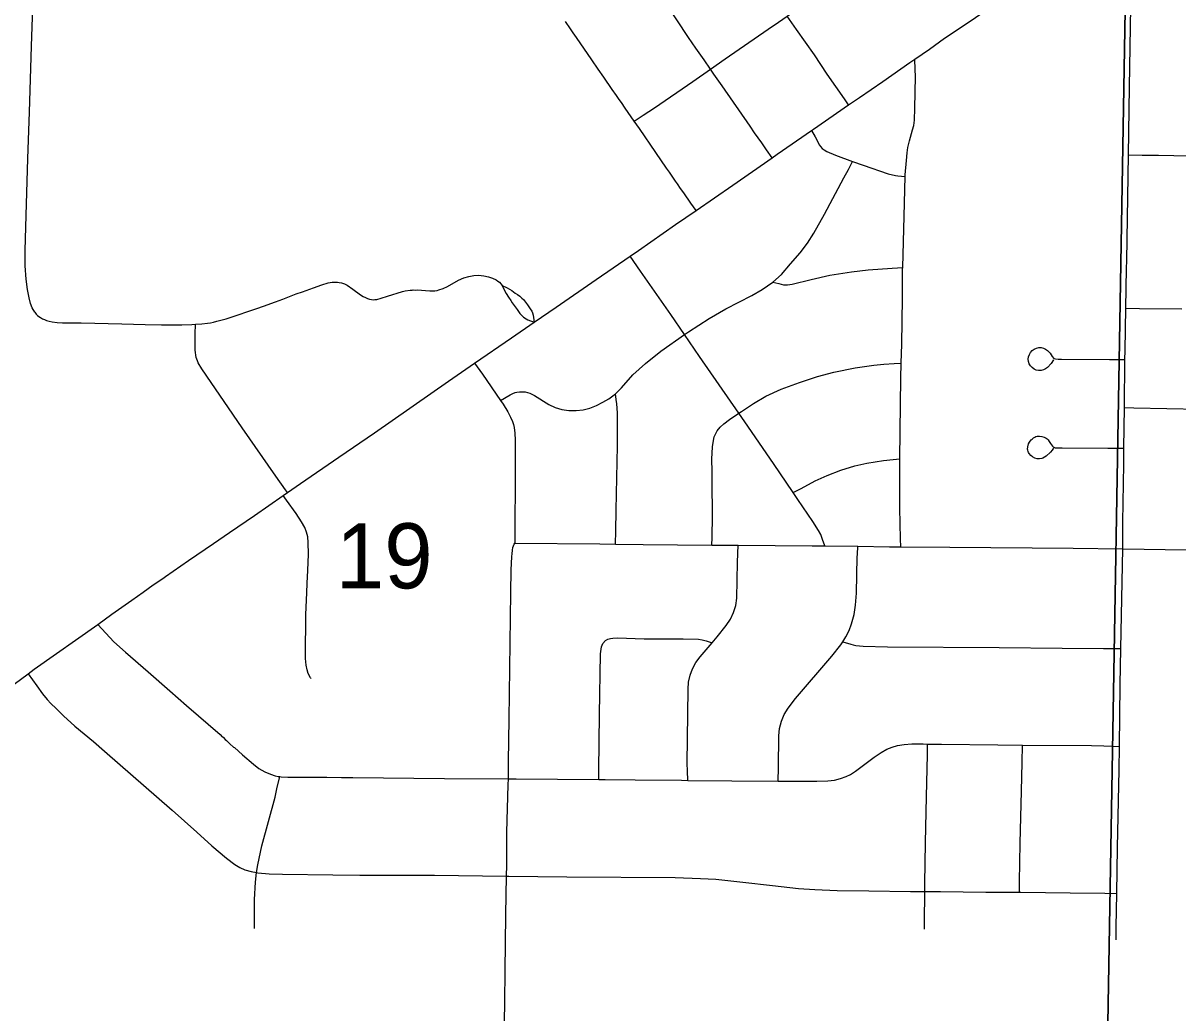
# Model space of a CAD drawing. Extents: x 0 to 34, y 0 to 22.
# Drawn here: x 5.989 to 6.731, y 16.761 to 17.398 of the extents above; entities that cross this region are included whole.
import ezdxf

# ---------------------------------------------------------------- set-up
doc = ezdxf.new("R2010")
doc.units = 0
for name, color, linetype in [('GM_X_City_Street', 7, 'Continuous'), ('GM_X_Corporation', 7, 'Continuous'), ('GM_X_County_Road', 7, 'Continuous'), ('GM_X_Section_Text', 7, 'Continuous')]:
    doc.layers.add(name, color=color, linetype=linetype)

msp = doc.modelspace()

# ---------------------------------------------------------------- linework, layer by layer
at = {"layer": 'GM_X_City_Street'}
for points in [[(6.38189, 17.33453), (6.38766, 17.33835), (6.39487, 17.34314), (6.4195, 17.35995), (6.43091, 17.36795), (6.44036, 17.37457), (6.46796, 17.39369), (6.47464, 17.39822), (6.48015, 17.402), (6.50541, 17.41931), (6.52913, 17.43567), (6.54378, 17.44578), (6.56925, 17.46352), (6.58463, 17.47403), (6.5991, 17.48358), (6.60985, 17.49085), (6.62182, 17.49957), (6.63111, 17.50666), (6.63429, 17.50944), (6.63584, 17.51122), (6.63775, 17.51441), (6.63892, 17.51638)], [(5.9964, 17.21165), (5.99476, 17.21456), (5.99369, 17.21737), (5.99271, 17.22088), (5.99163, 17.2263), (5.99074, 17.23302), (5.99027, 17.24148), (5.99027, 17.25128), (5.99077, 17.27388), (5.99199, 17.31055), (5.99292, 17.34039), (5.99424, 17.38264), (5.99507, 17.40749)], [(6.47049, 17.31094), (6.46694, 17.31599), (6.46384, 17.32051), (6.45924, 17.327), (6.45629, 17.33138), (6.43839, 17.35732), (6.4331, 17.36478), (6.43091, 17.36795), (6.42684, 17.3739), (6.42147, 17.38152), (6.41679, 17.38838), (6.4022, 17.41033)], [(6.42164, 17.27717), (6.41834, 17.2818), (6.41366, 17.28836), (6.4117, 17.29114), (6.40968, 17.29417), (6.40841, 17.29594), (6.40626, 17.2991), (6.40443, 17.30175), (6.40266, 17.3044), (6.39583, 17.31439), (6.38523, 17.32973), (6.38189, 17.33453), (6.37609, 17.34285), (6.37364, 17.34649), (6.37224, 17.34846), (6.37048, 17.35091), (6.36774, 17.35478), (6.36231, 17.3628), (6.3587, 17.36792), (6.35465, 17.37391), (6.34472, 17.38825), (6.34263, 17.39128), (6.34092, 17.3938), (6.33764, 17.39854)], [(6.51973, 17.34495), (6.51697, 17.34895), (6.50601, 17.36481), (6.49768, 17.37715), (6.48623, 17.39336), (6.48015, 17.402)], [(6.55323, 17.06089), (6.55312, 17.06606), (6.55268, 17.08567), (6.55256, 17.10743), (6.55266, 17.11748), (6.55304, 17.15246), (6.55333, 17.1694), (6.55359, 17.17887), (6.55392, 17.19114), (6.55433, 17.22068), (6.55444, 17.23935), (6.55448, 17.24041), (6.55551, 17.27354), (6.55613, 17.299), (6.55616, 17.29998), (6.55689, 17.30927), (6.55728, 17.31423), (6.55785, 17.31768), (6.55891, 17.32179), (6.5608, 17.32887), (6.56154, 17.33183), (6.56203, 17.3352), (6.56236, 17.34296), (6.5628, 17.36316), (6.5626, 17.36782), (6.56232, 17.37445)], [(6.49593, 17.32857), (6.49817, 17.32437), (6.50096, 17.31914), (6.50165, 17.31818), (6.50272, 17.31693), (6.50388, 17.31611), (6.50563, 17.31511), (6.51132, 17.3126), (6.5223, 17.30863), (6.52898, 17.30622), (6.54522, 17.30062), (6.54976, 17.29954), (6.55132, 17.29941), (6.55613, 17.299)], [(6.69967, 17.31278), (6.70843, 17.31268), (6.71892, 17.31257), (6.7288, 17.31245), (6.74446, 17.31198), (6.76906, 17.31145), (6.80488, 17.3108), (6.8106, 17.31058), (6.81482, 17.31042)], [(6.29592, 17.15499), (6.30204, 17.15853), (6.30385, 17.15954), (6.3053, 17.16011), (6.30635, 17.16032), (6.30808, 17.1605), (6.30994, 17.16054), (6.31161, 17.16041), (6.31312, 17.16007), (6.31475, 17.15955), (6.31769, 17.15816), (6.32694, 17.15236), (6.33101, 17.1504), (6.33536, 17.14916), (6.33986, 17.14852), (6.34442, 17.14846), (6.34893, 17.14895), (6.35335, 17.15005), (6.3576, 17.15167), (6.36163, 17.1538), (6.36554, 17.15612), (6.36892, 17.15852), (6.36972, 17.15929), (6.37356, 17.16303), (6.38103, 17.17142), (6.38919, 17.17872), (6.39892, 17.18658), (6.41418, 17.19733), (6.41679, 17.19917), (6.42997, 17.20756), (6.4408, 17.21378), (6.45756, 17.22242), (6.46419, 17.2264), (6.47088, 17.23107), (6.47651, 17.23596), (6.48242, 17.24286), (6.48852, 17.24985), (6.4932, 17.25598), (6.4974, 17.26245), (6.50415, 17.27466), (6.51659, 17.29804), (6.51954, 17.30353), (6.5223, 17.30863)], [(6.50443, 17.0615), (6.50289, 17.06565), (6.50174, 17.06877), (6.50039, 17.07143), (6.4966, 17.07712), (6.4871, 17.09129), (6.48403, 17.09579), (6.47134, 17.11439), (6.45298, 17.14119), (6.44912, 17.14676), (6.42387, 17.18323), (6.41418, 17.19733), (6.40539, 17.21013), (6.38579, 17.23817), (6.37917, 17.24765)], [(5.9964, 17.21165), (5.99729, 17.21051), (5.99819, 17.20956), (5.9989, 17.209), (6.00005, 17.20824), (6.00124, 17.20752), (6.00256, 17.20693), (6.00399, 17.20633), (6.00566, 17.20586), (6.00758, 17.20544), (6.01069, 17.20503), (6.01421, 17.20491), (6.01768, 17.20485), (6.02222, 17.2048), (6.02619, 17.20481), (6.05235, 17.20419), (6.06727, 17.20382), (6.07784, 17.20352), (6.09087, 17.20357), (6.0973, 17.20378), (6.09975, 17.20396), (6.10382, 17.20427), (6.10746, 17.2047), (6.10927, 17.20496), (6.11129, 17.20534), (6.11347, 17.20586), (6.1194, 17.2075), (6.12648, 17.20979), (6.1341, 17.21241), (6.13927, 17.21415), (6.14347, 17.21568), (6.1511, 17.21841), (6.15582, 17.22014), (6.16447, 17.22341), (6.16859, 17.2248), (6.17556, 17.22736), (6.18092, 17.22931), (6.18513, 17.23058), (6.18771, 17.23092), (6.19096, 17.23091), (6.19221, 17.23076), (6.19356, 17.23052), (6.19546, 17.23002), (6.19725, 17.22916), (6.20097, 17.22661), (6.20588, 17.22285), (6.20758, 17.22174), (6.209, 17.22105), (6.21039, 17.22043), (6.21166, 17.22004), (6.21284, 17.21983), (6.21395, 17.21976), (6.21512, 17.21983), (6.21626, 17.21996), (6.21914, 17.22062), (6.22319, 17.22205), (6.23277, 17.22503), (6.23464, 17.22546), (6.23782, 17.22587), (6.23909, 17.2259), (6.23973, 17.22604), (6.241, 17.22597), (6.24228, 17.22603), (6.25035, 17.22549), (6.25253, 17.22543), (6.25373, 17.22548), (6.25516, 17.22572), (6.25624, 17.226), (6.25903, 17.22694), (6.26175, 17.22828), (6.26886, 17.23222), (6.27236, 17.23376), (6.27543, 17.23472), (6.27861, 17.23528), (6.28184, 17.23543), (6.28337, 17.23537), (6.28505, 17.23517), (6.28822, 17.23452), (6.29069, 17.23366), (6.29303, 17.23248), (6.29413, 17.23173), (6.29516, 17.23091), (6.29698, 17.22897)], [(6.47088, 17.23107), (6.47492, 17.23005), (6.47784, 17.22933), (6.48036, 17.22927), (6.48347, 17.22973), (6.49558, 17.23273), (6.50769, 17.23545), (6.52146, 17.2377), (6.53224, 17.23894), (6.54774, 17.23996), (6.55448, 17.24041)], [(6.29698, 17.22897), (6.29821, 17.22619), (6.29958, 17.22379), (6.30107, 17.2213), (6.30241, 17.21929), (6.30343, 17.21781), (6.30659, 17.21335), (6.30837, 17.21089), (6.30969, 17.20945), (6.31065, 17.20856), (6.31226, 17.20748), (6.31352, 17.20682), (6.3174, 17.20521)], [(6.29698, 17.22897), (6.30023, 17.22731), (6.30316, 17.22558), (6.30538, 17.22403), (6.30687, 17.22301), (6.30818, 17.222), (6.3095, 17.22081), (6.31054, 17.21981), (6.31315, 17.21647), (6.31503, 17.21379), (6.31596, 17.21232), (6.31644, 17.21131), (6.31687, 17.20975), (6.31723, 17.2067), (6.3174, 17.20521)], [(6.69799, 17.2142), (6.70666, 17.2141), (6.73401, 17.21379)], [(6.15885, 17.09579), (6.15755, 17.09762), (6.15133, 17.10636), (6.12977, 17.13746), (6.11816, 17.15432), (6.1097, 17.16659), (6.10376, 17.17536), (6.10155, 17.17919), (6.10092, 17.18048), (6.10049, 17.18151), (6.10015, 17.18263), (6.09986, 17.18407), (6.09963, 17.18571), (6.09954, 17.18728), (6.09953, 17.19291), (6.09962, 17.19756), (6.09975, 17.20396)], [(6.6514, 17.18106), (6.65, 17.17875), (6.64758, 17.17622), (6.64633, 17.1753), (6.64494, 17.17463), (6.64345, 17.17427), (6.6419, 17.17425), (6.64038, 17.17454), (6.63895, 17.17515), (6.63769, 17.17605), (6.63666, 17.17721), (6.63588, 17.17855), (6.6354, 17.18002), (6.63525, 17.18156), (6.63544, 17.18309), (6.63594, 17.18455), (6.63674, 17.18588), (6.63781, 17.18702), (6.63907, 17.18795), (6.64047, 17.18863), (6.64198, 17.189), (6.64351, 17.189), (6.64499, 17.18865), (6.64637, 17.18799), (6.64758, 17.18703), (6.64924, 17.18537), (6.65066, 17.18315), (6.6516, 17.18187), (6.65282, 17.18167), (6.65443, 17.1816), (6.65665, 17.18147), (6.68756, 17.1813), (6.69742, 17.18122)], [(6.4318, 17.06197), (6.4319, 17.06684), (6.43198, 17.07079), (6.43214, 17.07696), (6.43212, 17.08483), (6.43204, 17.09875), (6.43197, 17.1094), (6.43183, 17.11717), (6.43214, 17.12517), (6.43276, 17.12914), (6.43334, 17.13148), (6.43383, 17.13277), (6.43526, 17.13536), (6.43716, 17.13778), (6.43937, 17.13994), (6.44315, 17.14267), (6.44912, 17.14676), (6.45084, 17.14793), (6.45846, 17.15306), (6.46655, 17.15763), (6.47643, 17.16215), (6.48805, 17.1666), (6.49979, 17.17043), (6.51024, 17.17317), (6.52392, 17.17601), (6.53595, 17.17756), (6.54244, 17.1783), (6.54902, 17.17864), (6.55359, 17.17887)], [(6.36979, 17.06262), (6.36993, 17.0712), (6.37014, 17.08429), (6.37034, 17.09492), (6.37099, 17.1257), (6.37114, 17.14695), (6.37065, 17.15281), (6.37025, 17.1556), (6.36972, 17.15929)], [(6.69704, 17.15043), (6.70302, 17.15031), (6.74562, 17.14944), (6.79588, 17.14861), (6.80641, 17.14836), (6.81355, 17.1482)], [(6.65142, 17.1243), (6.65053, 17.12305), (6.64948, 17.12166), (6.64671, 17.11913), (6.64572, 17.11844), (6.64468, 17.11793), (6.64395, 17.11775), (6.64244, 17.11748), (6.6409, 17.11754), (6.6394, 17.11793), (6.63803, 17.11864), (6.63683, 17.11962), (6.63585, 17.12084), (6.63539, 17.12156), (6.63516, 17.12223), (6.63494, 17.12294), (6.63482, 17.12373), (6.63493, 17.12525), (6.63542, 17.12714), (6.63598, 17.12821), (6.63647, 17.1289), (6.63712, 17.12965), (6.63764, 17.13015), (6.63855, 17.13089), (6.63942, 17.13141), (6.64015, 17.13174), (6.64088, 17.13193), (6.64242, 17.13205), (6.64396, 17.13184), (6.64544, 17.13139), (6.64679, 17.13064), (6.6474, 17.13026), (6.64797, 17.12964), (6.64874, 17.12857), (6.64948, 17.12737), (6.65023, 17.12634), (6.65078, 17.12559), (6.65127, 17.12509), (6.65252, 17.1246), (6.65385, 17.12454), (6.65693, 17.12444), (6.68646, 17.12437), (6.69673, 17.12434)], [(6.48403, 17.09579), (6.4891, 17.09847), (6.49814, 17.10325), (6.50594, 17.1067), (6.51468, 17.11022), (6.5237, 17.11296), (6.53136, 17.11468), (6.54221, 17.11631), (6.54843, 17.11701), (6.55266, 17.11748)], [(6.17402, 16.97616), (6.1737, 16.97669), (6.17227, 16.97946), (6.17148, 16.98181), (6.17085, 16.98485), (6.17048, 16.98919), (6.17043, 16.99789), (6.17071, 17.00969), (6.17073, 17.014), (6.17074, 17.01709), (6.17093, 17.02206), (6.17134, 17.03137), (6.17163, 17.03759), (6.172, 17.04566), (6.17234, 17.05621), (6.17225, 17.06366), (6.17189, 17.06737), (6.17117, 17.07038), (6.16997, 17.07324), (6.16784, 17.07703), (6.1644, 17.08222), (6.15824, 17.09084), (6.15607, 17.09387)], [(6.29804, 16.73136), (6.29857, 16.76804), (6.29878, 16.78854), (6.29901, 16.80594), (6.29927, 16.82446), (6.29978, 16.84924), (6.29993, 16.85629), (6.29996, 16.87743), (6.30083, 16.90786), (6.3009, 16.91176), (6.3011, 16.92281), (6.30139, 16.95015), (6.30253, 17.03161), (6.3028, 17.04595), (6.30318, 17.05469), (6.30327, 17.05643), (6.30355, 17.05877), (6.30389, 17.06046), (6.30421, 17.06153), (6.30466, 17.06257), (6.30513, 17.06324)], [(6.41628, 16.91076), (6.41609, 16.91693), (6.41594, 16.92154), (6.41645, 16.96943), (6.41673, 16.97393), (6.41773, 16.97829), (6.41932, 16.98252), (6.4215, 16.98643), (6.42419, 16.99011), (6.43193, 16.99922), (6.43517, 17.00304), (6.44104, 17.01031), (6.44365, 17.01428), (6.44571, 17.01858), (6.44709, 17.02316), (6.44773, 17.02789), (6.44833, 17.05108), (6.4486, 17.06185)], [(6.47438, 16.91027), (6.47453, 16.91908), (6.47487, 16.9393), (6.47536, 16.94404), (6.47647, 16.94871), (6.47833, 16.95315), (6.48083, 16.95724), (6.4856, 16.96347), (6.50886, 16.99067), (6.51465, 16.9979), (6.51595, 16.99987), (6.518, 17.00301), (6.52004, 17.00708), (6.52165, 17.01136), (6.52322, 17.01728), (6.52423, 17.02333), (6.52471, 17.031), (6.52529, 17.05434), (6.52537, 17.05591), (6.52565, 17.06122)], [(6.69169, 16.80834), (6.69178, 16.81627), (6.69215, 16.83803), (6.69267, 16.86768), (6.6936, 16.91756), (6.69381, 16.93254), (6.69436, 16.97211), (6.6948, 16.99544), (6.69598, 17.05952)], [(6.03683, 17.01101), (6.04732, 16.99976), (6.05462, 16.99322), (6.06919, 16.98061), (6.08319, 16.96828), (6.09398, 16.9589), (6.1156, 16.94016), (6.11692, 16.93883), (6.11742, 16.93846), (6.11873, 16.93712), (6.11969, 16.93635), (6.12191, 16.93415), (6.12427, 16.93215), (6.12479, 16.93181), (6.12988, 16.92722), (6.137, 16.92114), (6.14055, 16.91848), (6.1444, 16.91623), (6.14791, 16.91465), (6.15098, 16.9137), (6.15292, 16.91325), (6.15395, 16.91313), (6.15476, 16.91303), (6.15919, 16.91276), (6.17416, 16.91273), (6.18418, 16.91283), (6.19354, 16.91267), (6.20088, 16.91251), (6.25995, 16.91194), (6.3009, 16.91176), (6.30597, 16.91174), (6.35899, 16.91133), (6.36318, 16.9113), (6.38245, 16.91106), (6.4123, 16.9108), (6.41628, 16.91076), (6.44464, 16.91046), (6.47438, 16.91027), (6.47759, 16.91025), (6.49937, 16.91017), (6.50628, 16.91038), (6.5107, 16.91094), (6.51442, 16.91184), (6.51803, 16.91316), (6.52089, 16.9146), (6.52407, 16.91667), (6.53608, 16.9256), (6.54063, 16.92872), (6.54435, 16.93075), (6.54771, 16.93212), (6.55119, 16.93314), (6.55538, 16.93384), (6.56026, 16.93418), (6.56768, 16.93413), (6.57053, 16.9341), (6.57949, 16.93403), (6.61556, 16.93362), (6.63143, 16.93348), (6.67587, 16.93308), (6.68392, 16.93284), (6.69381, 16.93254)], [(6.35899, 16.91133), (6.35908, 16.91724), (6.35958, 16.95318), (6.36022, 16.99218), (6.36073, 16.99662), (6.36174, 16.99864), (6.36339, 17.00062), (6.36487, 17.00153), (6.36651, 17.00194), (6.36813, 17.00217), (6.37115, 17.0023), (6.38829, 17.00179), (6.41331, 17.0017), (6.42308, 17.00143), (6.42563, 17.00111), (6.4281, 17.00037), (6.43193, 16.99922)], [(6.51595, 16.99987), (6.52105, 16.99829), (6.52264, 16.9978), (6.52425, 16.99751), (6.52899, 16.9971), (6.54464, 16.99669), (6.61643, 16.9961), (6.65702, 16.99569), (6.68354, 16.99552), (6.6948, 16.99544)], [(5.99214, 16.9793), (5.99767, 16.9715), (6.00125, 16.96643), (6.00427, 16.96273), (6.00673, 16.96019), (6.01013, 16.95688), (6.01484, 16.95231), (6.02221, 16.94569), (6.03419, 16.93571), (6.04129, 16.92962), (6.08483, 16.89154), (6.10055, 16.8774), (6.11023, 16.86867), (6.11967, 16.86064), (6.12507, 16.85656), (6.12816, 16.85471), (6.13149, 16.85333), (6.13557, 16.8521), (6.13891, 16.85146), (6.13975, 16.8513), (6.14705, 16.85065), (6.15575, 16.85038), (6.18809, 16.8501), (6.20549, 16.84978), (6.25337, 16.84973), (6.29978, 16.84924), (6.30125, 16.84922), (6.33855, 16.84881), (6.4082, 16.84821), (6.42438, 16.84769), (6.43434, 16.84715), (6.4517, 16.84539), (6.47084, 16.84312), (6.4875, 16.84134), (6.49801, 16.84058), (6.51227, 16.84003), (6.53277, 16.83971), (6.55949, 16.83937), (6.56874, 16.83931), (6.57876, 16.83925), (6.60799, 16.83896), (6.62959, 16.83877), (6.63037, 16.83877), (6.66208, 16.83843), (6.68447, 16.83813), (6.69215, 16.83803)], [(6.56857, 16.81511), (6.56856, 16.81947), (6.56874, 16.83931), (6.56878, 16.84438), (6.56914, 16.87052), (6.56978, 16.90041), (6.57037, 16.92717), (6.57053, 16.9341)], [(6.62959, 16.83877), (6.62968, 16.8455), (6.62998, 16.87027), (6.6308, 16.90371), (6.6312, 16.92229), (6.63143, 16.93348)], [(6.13767, 16.81554), (6.13775, 16.8342), (6.13828, 16.84538), (6.13891, 16.85146), (6.13973, 16.85647), (6.14248, 16.8686), (6.15085, 16.89984), (6.15212, 16.90528), (6.15395, 16.91313)]]:
    msp.add_lwpolyline(points, dxfattribs=at)
at = {"layer": 'GM_X_Corporation'}
for points in [[(5.75845, 17.5867), (6.70042, 17.56893), (6.68286, 16.55378), (5.74588, 16.55703), (5.75807, 17.55374)], [(6.70042, 17.56893), (7.70158, 17.53728), (7.6999, 16.53694), (6.68286, 16.55378)]]:
    msp.add_lwpolyline(points, close=True, dxfattribs=at)
at = {"layer": 'GM_X_County_Road'}
for p, q in [((6.69854, 17.24484), (6.69967, 17.31278)), ((6.69704, 17.15043), (6.69742, 17.18122)), ((6.69673, 17.12434), (6.69704, 17.15043)), ((6.15607, 17.09387), (6.15885, 17.09579)), ((6.50443, 17.0615), (6.52565, 17.06122))]:
    msp.add_line(p, q, dxfattribs=at)
for points in [[(6.56232, 17.37445), (6.57171, 17.38089), (6.58145, 17.38785), (6.59777, 17.39887), (6.60463, 17.40347), (6.61581, 17.41097), (6.62709, 17.41883), (6.63828, 17.42651), (6.661, 17.44232), (6.67156, 17.44973), (6.68824, 17.46102), (6.69861, 17.46807), (6.70175, 17.47028)], [(6.69967, 17.31278), (6.70039, 17.35634), (6.70167, 17.43396), (6.7017, 17.44523), (6.70182, 17.46261), (6.70175, 17.47028)], [(6.51973, 17.34495), (6.5268, 17.34981), (6.54168, 17.36011), (6.55917, 17.37231), (6.56232, 17.37445)], [(6.49593, 17.32857), (6.49712, 17.32939), (6.51973, 17.34495)], [(6.47049, 17.31094), (6.47376, 17.31322), (6.49593, 17.32857)], [(6.42164, 17.27717), (6.44535, 17.29343), (6.47049, 17.31094)], [(6.37917, 17.24765), (6.38465, 17.25142), (6.40846, 17.26813), (6.42164, 17.27717)], [(6.3174, 17.20521), (6.33171, 17.21501), (6.35732, 17.23263), (6.37917, 17.24765)], [(6.69799, 17.2142), (6.69846, 17.23985), (6.69854, 17.24484)], [(6.69742, 17.18122), (6.6975, 17.18706), (6.69799, 17.2142)], [(6.27922, 17.17887), (6.30294, 17.19531), (6.3174, 17.20521)], [(6.15885, 17.09579), (6.16729, 17.10162), (6.19191, 17.11843), (6.21491, 17.13424), (6.26235, 17.1673), (6.27922, 17.17887)], [(6.27922, 17.17887), (6.28418, 17.1719), (6.29592, 17.15499)], [(6.29592, 17.15499), (6.29765, 17.1525), (6.30066, 17.14771), (6.30239, 17.14432), (6.30354, 17.14135), (6.30415, 17.1396), (6.30454, 17.13766), (6.30513, 17.13388), (6.30536, 17.12946), (6.30537, 17.11142), (6.30523, 17.09961), (6.30505, 17.07691), (6.30513, 17.06324)], [(6.69598, 17.05952), (6.69602, 17.069), (6.69606, 17.07676), (6.6966, 17.11403), (6.69673, 17.12434)], [(6.05886, 17.02659), (6.0661, 17.03178), (6.0725, 17.03639), (6.07866, 17.04061), (6.08046, 17.04184), (6.09532, 17.05202), (6.11129, 17.06304), (6.12156, 17.07009), (6.13762, 17.08111), (6.15607, 17.09387)], [(6.30513, 17.06324), (6.35972, 17.06271), (6.36979, 17.06262)], [(6.36979, 17.06262), (6.38768, 17.06246), (6.4318, 17.06197)], [(6.4318, 17.06197), (6.43735, 17.06191), (6.4486, 17.06185)], [(6.4486, 17.06185), (6.49636, 17.0616), (6.50443, 17.0615)], [(6.52565, 17.06122), (6.54605, 17.06096), (6.55323, 17.06089)], [(6.55323, 17.06089), (6.58485, 17.06061), (6.66404, 17.06005), (6.69598, 17.05952)], [(6.69598, 17.05952), (6.73699, 17.05884), (6.75389, 17.05848)], [(6.03683, 17.01101), (6.046, 17.01756), (6.05886, 17.02659)], [(5.99214, 16.9793), (5.99605, 16.98226), (6.03683, 17.01101)], [(5.95279, 16.94667), (5.95945, 16.95281), (5.97022, 16.96208), (5.98321, 16.97255), (5.99214, 16.9793)]]:
    msp.add_lwpolyline(points, dxfattribs=at)

# ---------------------------------------------------------------- texts
at = {"layer": 'GM_X_Section_Text'}
msp.add_text('19', height=0.041856, rotation=0.00001, dxfattribs=at).set_placement((6.18997, 17.03416))

doc.saveas('drawing.dxf')
